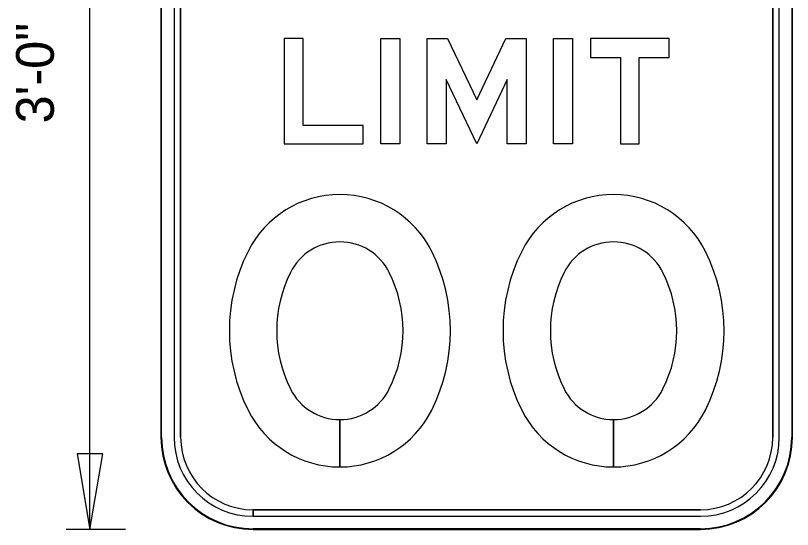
# Model space of a CAD drawing. Extents: x 0 to 770, y 0 to 495.
# Drawn here: x 433.9 to 505.9, y 221.4 to 269.1 of the extents above; entities that cross this region are included whole.
import ezdxf

# ---------------------------------------------------------------- set-up
doc = ezdxf.new("R2010")
doc.units = 0
for name, color, linetype in [('Dimension', 7, 'Continuous'), ('GSBWFill', 7, 'Continuous'), ('GSColorFill', 7, 'Continuous'), ('GSDims', 7, 'Continuous'), ('GSOutline', 7, 'Continuous'), ('TextStructures', 7, 'Continuous')]:
    doc.layers.add(name, color=color, linetype=linetype)

msp = doc.modelspace()

# ---------------------------------------------------------------- linework, layer by layer
at = {"layer": 'Dimension'}
msp.add_lwpolyline([(440.759, 221.42), (441.948, 228.437), (439.571, 228.437)], close=True, dxfattribs=at)
at = {"layer": 'GSBWFill'}
for p, q in [((447.348, 300.73), (447.348, 229.961)), ((448.568, 300.73), (448.568, 229.961)), ((449.178, 229.961), (449.178, 300.73)), ((504.085, 300.73), (504.085, 229.961)), ((504.695, 229.961), (504.695, 300.73)), ((505.915, 229.961), (505.915, 300.73)), ((463.942, 227.216), (463.942, 231.609)), ((463.943, 231.609), (463.943, 227.216)), ((489.321, 227.216), (489.321, 231.609)), ((489.322, 231.609), (489.322, 227.216)), ((455.889, 222.64), (455.889, 223.251)), ((497.374, 223.251), (455.895, 223.251)), ((455.895, 223.251), (455.895, 222.64)), ((455.895, 222.64), (497.374, 222.64)), ((455.889, 221.42), (497.374, 221.42))]:
    msp.add_line(p, q, dxfattribs=at)
for points in [[(466.09, 257.171), (466.09, 258.879), (460.526, 258.879), (460.526, 266.932), (458.769, 266.932), (458.769, 257.171)], [(467.749, 257.171), (467.749, 266.932), (469.506, 266.932), (469.506, 257.171)], [(476.632, 261.263), (479.327, 266.932), (481.219, 266.932), (481.219, 257.171), (479.462, 257.171), (479.462, 263.125), (476.632, 257.171), (473.801, 263.125), (473.801, 257.171), (472.044, 257.171), (472.044, 266.932), (473.937, 266.932)], [(483.757, 257.171), (483.757, 266.932), (485.514, 266.932), (485.514, 257.171)], [(487.174, 265.175), (489.956, 265.175), (489.956, 257.171), (491.713, 257.171), (491.713, 265.175), (494.495, 265.175), (494.495, 266.932), (487.174, 266.932)]]:
    msp.add_lwpolyline(points, close=True, dxfattribs=at)
for centre, radius, start, end in [((463.942, 242.956), 9.517, 26.48104, 153.51896), ((489.321, 242.956), 9.517, 26.48104, 153.51896), ((463.942, 242.956), 5.125, 26.48104, 153.51896), ((489.321, 242.956), 5.125, 26.48104, 153.51896), ((470.188, 239.845), 16.495, 153.51896, 206.48104), ((457.697, 239.845), 16.495, 333.51896, 26.48104), ((495.567, 239.845), 16.495, 153.51896, 206.48104), ((483.076, 239.845), 16.495, 333.51896, 26.48104), ((470.188, 239.845), 12.102, 153.51896, 206.48104), ((457.697, 239.845), 12.102, 333.51896, 26.48104), ((495.567, 239.845), 12.102, 153.51896, 206.48104), ((483.076, 239.845), 12.102, 333.51896, 26.48104), ((463.942, 236.733), 5.125, 206.48104, 270), ((463.942, 236.733), 5.125, 270.01364, 333.51896), ((489.321, 236.733), 5.125, 206.48104, 270), ((489.321, 236.733), 5.125, 270.01364, 333.51896), ((463.942, 236.733), 9.517, 206.48104, 270), ((463.942, 236.733), 9.517, 270.00734, 333.51896), ((489.321, 236.733), 9.517, 206.48104, 270), ((489.321, 236.733), 9.517, 270.00734, 333.51896), ((455.889, 229.961), 8.541, 180, 270), ((455.889, 229.961), 7.321, 180, 270), ((455.889, 229.961), 6.711, 180, 270), ((497.374, 229.961), 7.321, 270, 0), ((497.374, 229.961), 6.711, 270, 0), ((497.374, 229.961), 8.541, 270, 0)]:
    msp.add_arc(centre, radius, start, end, dxfattribs=at)
at = {"layer": 'GSColorFill'}
for p, q in [((447.348, 300.73), (447.348, 229.961)), ((447.348, 300.73), (447.348, 229.961)), ((447.409, 229.961), (447.409, 300.73)), ((448.568, 300.73), (448.568, 229.961)), ((449.178, 229.961), (449.178, 300.73)), ((504.085, 300.73), (504.085, 229.961)), ((504.695, 229.961), (504.695, 300.73)), ((505.854, 300.73), (505.854, 229.961)), ((505.915, 229.961), (505.915, 300.73)), ((505.915, 229.961), (505.915, 300.73)), ((463.942, 227.216), (463.942, 231.609)), ((463.943, 231.609), (463.943, 227.216)), ((489.321, 227.216), (489.321, 231.609)), ((489.322, 231.609), (489.322, 227.216)), ((455.889, 222.64), (455.889, 223.251)), ((497.374, 223.251), (455.895, 223.251)), ((455.895, 223.251), (455.895, 222.64)), ((455.895, 222.64), (497.374, 222.64)), ((455.889, 221.42), (455.889, 221.481)), ((455.889, 221.42), (497.374, 221.42)), ((497.374, 221.481), (455.89, 221.481)), ((455.89, 221.481), (455.89, 221.42)), ((455.89, 221.42), (497.374, 221.42))]:
    msp.add_line(p, q, dxfattribs=at)
for points in [[(466.09, 257.171), (466.09, 258.879), (460.526, 258.879), (460.526, 266.932), (458.769, 266.932), (458.769, 257.171)], [(467.749, 257.171), (467.749, 266.932), (469.506, 266.932), (469.506, 257.171)], [(476.632, 261.263), (479.327, 266.932), (481.219, 266.932), (481.219, 257.171), (479.462, 257.171), (479.462, 263.125), (476.632, 257.171), (473.801, 263.125), (473.801, 257.171), (472.044, 257.171), (472.044, 266.932), (473.937, 266.932)], [(483.757, 257.171), (483.757, 266.932), (485.514, 266.932), (485.514, 257.171)], [(487.174, 265.175), (489.956, 265.175), (489.956, 257.171), (491.713, 257.171), (491.713, 265.175), (494.495, 265.175), (494.495, 266.932), (487.174, 266.932)]]:
    msp.add_lwpolyline(points, close=True, dxfattribs=at)
for centre, radius, start, end in [((463.942, 242.956), 9.517, 26.48104, 153.51896), ((489.321, 242.956), 9.517, 26.48104, 153.51896), ((463.942, 242.956), 5.125, 26.48104, 153.51896), ((489.321, 242.956), 5.125, 26.48104, 153.51896), ((470.188, 239.845), 16.495, 153.51896, 206.48104), ((457.697, 239.845), 16.495, 333.51896, 26.48104), ((495.567, 239.845), 16.495, 153.51896, 206.48104), ((483.076, 239.845), 16.495, 333.51896, 26.48104), ((470.188, 239.845), 12.102, 153.51896, 206.48104), ((457.697, 239.845), 12.102, 333.51896, 26.48104), ((495.567, 239.845), 12.102, 153.51896, 206.48104), ((483.076, 239.845), 12.102, 333.51896, 26.48104), ((463.942, 236.733), 5.125, 206.48104, 270), ((463.942, 236.733), 5.125, 270.01364, 333.51896), ((489.321, 236.733), 5.125, 206.48104, 270), ((489.321, 236.733), 5.125, 270.01364, 333.51896), ((463.942, 236.733), 9.517, 206.48104, 270), ((463.942, 236.733), 9.517, 270.00734, 333.51896), ((489.321, 236.733), 9.517, 206.48104, 270), ((489.321, 236.733), 9.517, 270.00734, 333.51896), ((455.889, 229.961), 8.541, 180, 270), ((455.889, 229.961), 8.541, 180, 270), ((455.889, 229.961), 8.48, 180, 270), ((455.889, 229.961), 7.321, 180, 270), ((455.889, 229.961), 6.711, 180, 270), ((497.374, 229.961), 8.541, 270, 0), ((497.374, 229.961), 7.321, 270, 0), ((497.374, 229.961), 6.711, 270, 0), ((497.374, 229.961), 8.541, 270, 0), ((497.374, 229.961), 8.48, 270, 0)]:
    msp.add_arc(centre, radius, start, end, dxfattribs=at)
at = {"layer": 'GSDims'}
for p, q in [((440.759, 221.42), (440.759, 309.271)), ((444.054, 221.42), (438.563, 221.42))]:
    msp.add_line(p, q, dxfattribs=at)
at = {"layer": 'GSOutline'}
for p, q in [((447.348, 300.73), (447.348, 229.961)), ((448.568, 300.73), (448.568, 229.961)), ((449.178, 300.73), (449.178, 229.961)), ((504.085, 229.961), (504.085, 300.73)), ((504.695, 229.961), (504.695, 300.73)), ((505.915, 229.961), (505.915, 300.73)), ((455.889, 223.251), (497.374, 223.251)), ((455.889, 222.64), (497.374, 222.64)), ((455.889, 221.42), (497.374, 221.42))]:
    msp.add_line(p, q, dxfattribs=at)
for points in [[(466.09, 257.171), (466.09, 258.879), (460.526, 258.879), (460.526, 266.932), (458.769, 266.932), (458.769, 257.171)], [(467.749, 257.171), (467.749, 266.932), (469.506, 266.932), (469.506, 257.171)], [(476.632, 261.263), (479.327, 266.932), (481.219, 266.932), (481.219, 257.171), (479.462, 257.171), (479.462, 263.125), (476.632, 257.171), (473.801, 263.125), (473.801, 257.171), (472.044, 257.171), (472.044, 266.932), (473.937, 266.932)], [(483.757, 257.171), (483.757, 266.932), (485.514, 266.932), (485.514, 257.171)], [(487.174, 265.175), (489.956, 265.175), (489.956, 257.171), (491.713, 257.171), (491.713, 265.175), (494.495, 265.175), (494.495, 266.932), (487.174, 266.932)]]:
    msp.add_lwpolyline(points, close=True, dxfattribs=at)
for centre, radius, start, end in [((463.942, 242.956), 9.517, 26.48104, 153.51896), ((489.321, 242.956), 9.517, 26.48104, 153.51896), ((463.942, 242.956), 5.125, 26.48104, 153.51896), ((489.321, 242.956), 5.125, 26.48104, 153.51896), ((470.188, 239.845), 16.495, 153.51896, 206.48104), ((457.697, 239.845), 16.495, 333.51896, 26.48104), ((495.567, 239.845), 16.495, 153.51896, 206.48104), ((483.076, 239.845), 16.495, 333.51896, 26.48104), ((470.188, 239.845), 12.102, 153.51896, 206.48104), ((457.697, 239.845), 12.102, 333.51896, 26.48104), ((495.567, 239.845), 12.102, 153.51896, 206.48104), ((483.076, 239.845), 12.102, 333.51896, 26.48104), ((463.942, 236.733), 5.125, 206.48104, 333.51896), ((489.321, 236.733), 5.125, 206.48104, 333.51896), ((463.942, 236.733), 9.517, 206.48104, 333.51896), ((489.321, 236.733), 9.517, 206.48104, 333.51896), ((455.889, 229.961), 8.541, 180, 270), ((455.889, 229.961), 7.321, 180, 270), ((455.889, 229.961), 6.711, 180, 270), ((497.374, 229.961), 7.321, 270, 0), ((497.374, 229.961), 6.711, 270, 0), ((497.374, 229.961), 8.541, 270, 0)]:
    msp.add_arc(centre, radius, start, end, dxfattribs=at)

# ---------------------------------------------------------------- texts
at = {"layer": 'TextStructures'}
msp.add_text('3\'-0"', height=3.5, rotation=90, dxfattribs=at).set_placement((437.416, 259.063))

doc.saveas('drawing.dxf')
